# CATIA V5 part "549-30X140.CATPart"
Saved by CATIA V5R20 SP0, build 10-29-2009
Part number: 549-30X140
Definition: NONE
Nomenclature: 549-30X140
Source: Unknown
Description: 549-30X140
Bounding box of the stored display mesh (mm): x 0 to 140, y -17.5 to 17.5, z -17.5 to 17.5
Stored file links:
  C:\Users\Utente\Desktop\IO LAVORO\3D X SITO CF\X SITO\PLASTICA\549\549-30X140.CATPart
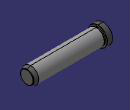
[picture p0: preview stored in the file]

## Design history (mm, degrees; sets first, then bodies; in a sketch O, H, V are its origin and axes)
Body1 "549-30X140" (main body)
  Solid1: solid without history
